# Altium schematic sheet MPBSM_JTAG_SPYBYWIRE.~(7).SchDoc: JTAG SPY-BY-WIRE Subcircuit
size 431 x 279 mm; Date: Not shown in title block; ApprovedBy: Not shown in title block; CheckedBy: Not shown in title block; Author: Not shown in title block; CompanyName: Not shown in title block; Engineer: Not shown in title block; Organization: Not shown in title block; Address1: Not shown in title block; Address2: Not shown in title block; Address3: Not shown in title block; Address4: Not shown in title block; DocumentNumber: 5; Revision: Use project parameter SCH_Rev; SheetNumber: 5; SheetTotal: 12; PageSetup: Record=PageOptions¦CenterHorizontal=True¦CenterVertical=True¦PrintScale=0.62¦XCorrection=1.00¦YCorrection=1.00¦PrintKind=0¦BorderSize=5000000¦LeftOffset=0¦BottomOffset=0¦Orientation=2¦PaperLength=1000¦PaperWidth=1000¦Scale=100¦PaperSource=15¦PrintQuality=600¦MediaType=1¦DitherType=10¦PaperKind=Letter¦PrintScaleMode=1
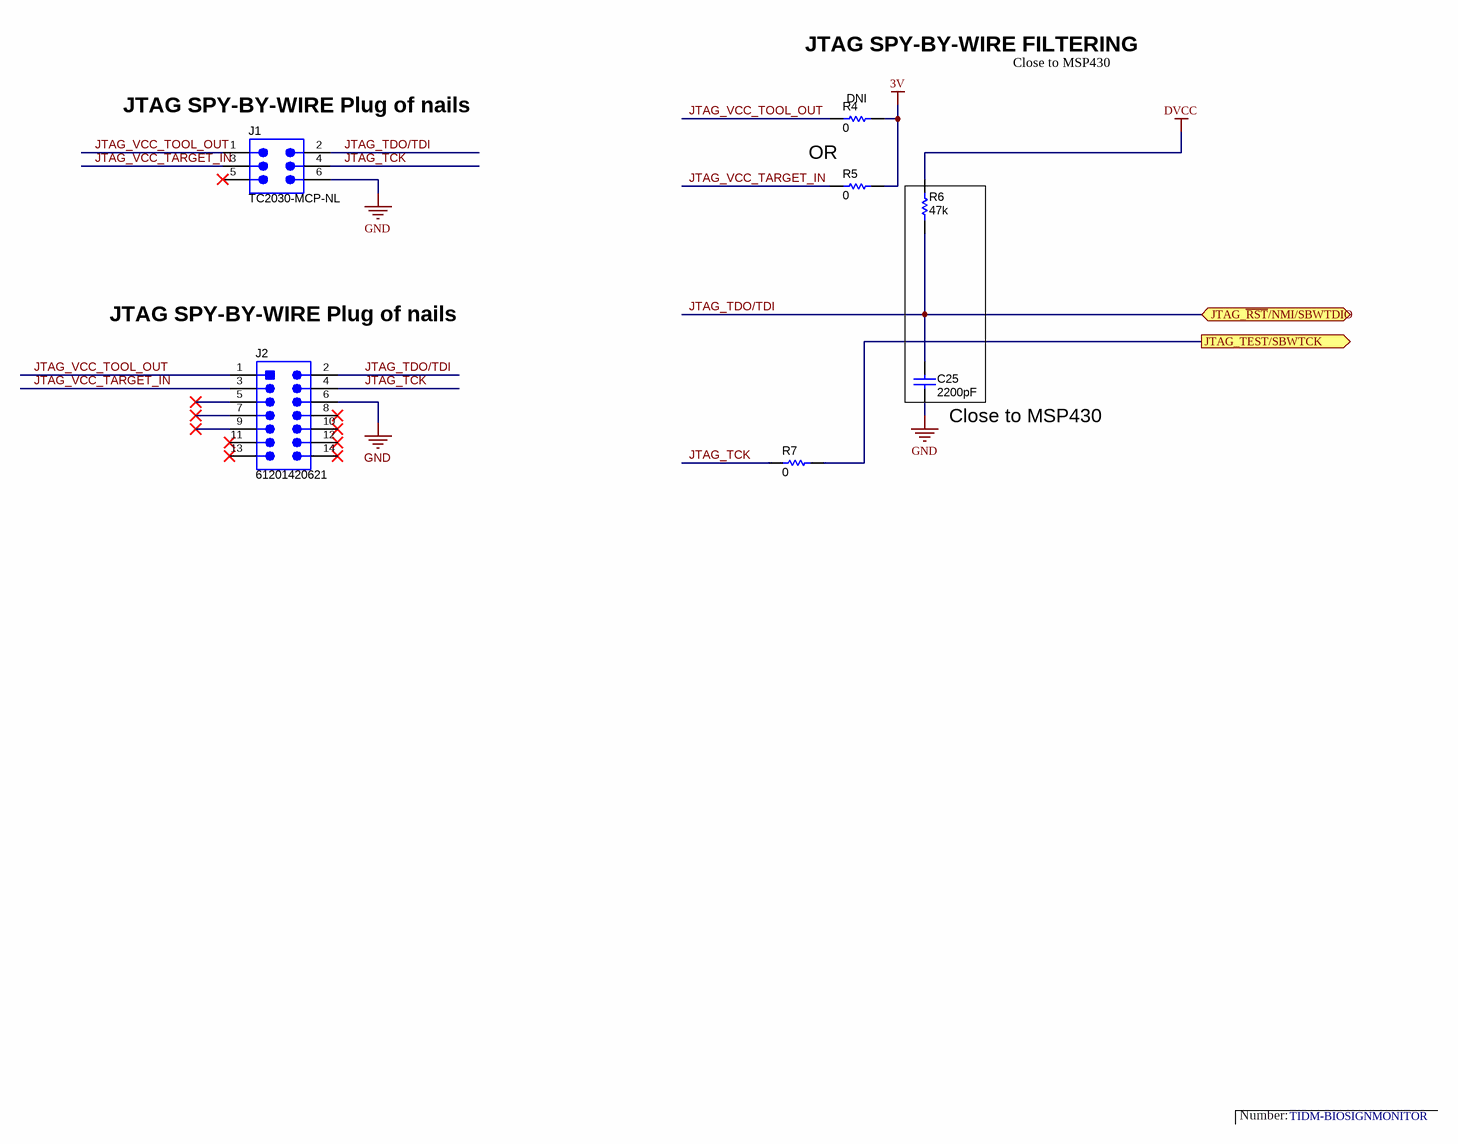
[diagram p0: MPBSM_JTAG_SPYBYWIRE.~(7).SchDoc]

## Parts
C25  ValueDisplayed: 2200pF  [0402]  (hidden comment: C1005X8R1H222K)
J1  TC2030-MCP-NL  [TC2030-MCP-NL]  (no BOM)
J2  61201420621  [Wurth_61201420621]
R4  ValueDisplayed: 0  [0402]  (hidden comment: ERJ-2GE0R00X)
R5  ValueDisplayed: 0  [0402]  (hidden comment: ERJ-2GE0R00X)
R6  ValueDisplayed: 47k  [0402]  (hidden comment: CRCW040247K0JNED)
R7  ValueDisplayed: 0  [0402]  (hidden comment: ERJ-2GE0R00X)

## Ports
JTAG_TEST/SBWTCK (out), JTAG_~{RST}/NMI/SBWTDIO (bidir)

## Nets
3V: R4.2 R5.2
DVCC: R6.2
GND: C25.2 J1.6 J2.6
JTAG_TCK: J1.4 J2.4 R7.1
JTAG_TDO/TDI: C25.1 J1.2 J2.2 R6.1 ; port JTAG_~{RST}/NMI/SBWTDIO
JTAG_TEST/SBWTCK: R7.2 ; port JTAG_TEST/SBWTCK
JTAG_VCC_TARGET_IN: J1.3 J2.3 R5.1
JTAG_VCC_TOOL_OUT: J1.1 J2.1 R4.1

Not connected (* = marked no-connect by the designer): J1 5*; J2 5* 7* 8* 9* 10* 11* 12* 13* 14*

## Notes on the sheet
- JTAG SPY-BY-WIRE FILTERING
- Close to MSP430
- (near J1) JTAG SPY-BY-WIRE Plug of nails
- OR
- (near R4) DNI
- (near J2) JTAG SPY-BY-WIRE Plug of nails
- (near C25) Close to MSP430
- Number:
- TIDM-BIOSIGNMONITOR

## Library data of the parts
C25 = C1005X8R1H222K: CAP, CERM, 2200 pF, 50 V, +/- 10%, X8R, 0402; Manufacturer: TDK; Polarized: N; CompType: Capacitor; Value: 2200pF; U/M: EA; Cap_F: 0.0000000022; Tolerance_%: 10; ESR_ohm: 0.1736; Value1: 0.1736 ohm; VDC_V: 50; Value2: 50V; TaMin_C: -55; TaMax_C: 150
J1 = TC2030-MCP-NL: Footprint for TC2030-MCP-NL; Manufacturer: Tag-Connect; SymbolCreator: a0799628; Note: Footprint only, to mate with Tag-Connect cable P/N TC2030-MCP-NL; CompType: Receptacle; U/M: EA
J2 = 61201420621: Header(Shrouded), 2.54mm, 7x2, Gold, Black, SMT; Manufacturer: Wurth Elektronik; SymbolCreator: a0412235; Pitch_mm: 2.54; Gender: Male; Shrouded: Y; Row_Count: 2; Current_A: 3; Voltage_V: 250
R4 R5 R7 = ERJ-2GE0R00X: RES, 0, 5%, 0.063 W, 0402; Manufacturer: Panasonic; CompType: Resistor; Value: 0; Value_Code: 0000; Tolerance_%: 5; Power_W: 0.063; Value2: 0.063W; VDC_V: 50; TempCo: 600 ppm/C; EIA_Code: E24; U/M: EA
R6 = CRCW040247K0JNED: RES, 47 k, 5%, 0.063 W, 0402; Manufacturer: Vishay-Dale; CompType: Resistor; Value: 47k; Res_ohm: 47000; Value_Code: 47k0; Tolerance_%: 5; Power_W: 0.063; Value2: 0.063W; VDC_V: 50; TempCo: 200 ppm/C; EIA_Code: E24; U/M: EA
